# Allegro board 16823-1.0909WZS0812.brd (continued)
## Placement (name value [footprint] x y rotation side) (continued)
PC1014  SC22U6D3V3MX-1-GP  [C603H40]  113.52 118.72 270 top
PC1015  SC22U6D3V3MX-1-GP  [C603H40]  113.52 117.43 270 top
PC1016  SC22U6D3V3MX-1-GP  [C603H40]  113.11 115.57 180 top
PC1017  SC22U6D3V3MX-1-GP  [C603H40]  110.52 114.94 180 top
PC1018  SC22U6D3V3MX-1-GP  [C603H40]  111.82 114.94 179.7 top
PC1019  SC22U6D3V3MX-1-GP  [C603H40]  109.86 111.81 270 top
PC1020  SC22U6D3V3MX-1-GP  [C603H40]  121.5 118.87 89.9 top
PC1021  SC22U6D3V3MX-1-GP  [C603H40]  121.49 117.6 90 top
PC1022  SC22U6D3V3MX-1-GP  [C603H40]  121.5 116.31 90 top
PC1023  SCD1U25V2KX-GP  [C402H22]  123.38 85.3 110 top
PC1024  SC22U6D3V3MX-1-GP  [C603H40]  121.5 115.01 90 top
PC1025  SC22U6D3V3MX-1-GP  [C603H40]  121.5 113.72 89.9 top
PC1026  SC22U6D3V3MX-1-GP  [C603H40]  121.72 109.73 90 top
PC1027  SC22U6D3V3MX-1-GP  [C603H40]  143.09 80.09 90 top
PC1028  SC22U6D3V3MX-1-GP  [C603H40]  109.86 110.52 270 top
PC1030  SC22U6D3V3MX-1-GP  [C603H40]  117.86 106.91 20 bottom
PC1031  SC22U6D3V3MX-1-GP  [C603H40]  114.15 105.52 20 bottom
PC1032  SC22U6D3V3MX-1-GP  [C603H40]  116.65 106.45 20 bottom
PC1033  SC22U6D3V3MX-1-GP  [C603H40]  119.11 107.36 20 bottom
PC1034  SC22U6D3V3MX-1-GP  [C603H40]  113.11 115.57 0.2 bottom
PC1035  SC22U6D3V3MX-1-GP  [C603H40]  111.82 114.94 0 bottom
PC1036  SC22U6D3V3MX-1-GP  [C603H40]  120.32 107.83 20 bottom
PC1037  SC22U6D3V3MX-1-GP  [C603H40]  115.4 106 20 bottom
PC1038  SCD1U25V2KX-GP  [C402H22]  109.79 108.59 270 top
PC1039  SC22U6D3V3MX-1-GP  [C603H40]  110.52 114.94 0 bottom
PC1040  SC22U6D3V3MX-1-GP  [C603H40]  140.24 106.81 0 bottom
PC1041  SC22U6D3V3MX-1-GP  [C603H40]  125.91 93.93 290 top
PC1042  SC22U6D3V3MX-1-GP  [C603H40]  143.31 87.2 0 top
PC1043  SC22U6D3V3MX-1-GP  [C603H40]  144.81 85.32 180 top
PC1044  SC22U6D3V3MX-1-GP  [C603H40]  109.86 113.11 269.9 top
PC1045  SC22U6D3V3MX-1-GP  [C603H40]  125.77 84.39 200 top
PC1046  SC22U6D3V3MX-1-GP  [C603H40]  143.72 90.88 180.1 top
PC1047  SC10U6D3V3MX-GP  [C603H38]  139.22 81.43 90 top
PC1048  SC22U6D3V3MX-1-GP  [C603H40]  102.6 115.54 270 top
PC1049  SC22U6D3V3MX-1-GP  [C603H40]  102.6 114.27 270 top
PC1050  SC22U6D3V3MX-1-GP  [C603H40]  121.25 82.8 20 top
PC1051  SC22U6D3V3MX-1-GP  [C603H40]  107.3 114 90 top
PC1052  SC10U6D3V3MX-GP  [C603H38]  143.06 78.77 90 top
PC1101  SC1U10V2KX-1GP  [C402H22]  127.24 87.28 290 top
PC1102  SC22U6D3V3MX-1-GP  [C603H40]  145.63 92.99 90.1 top
PC1103  SC22U6D3V3MX-1-GP  [C603H40]  118.96 88.19 110 top
PC4301  SC1U50V5ZY-1-GP-U  [C805H58]  137.55 163.32 270 top
PC4302  SCD1U50V3KX-GP  [C603H36]  140.29 172.11 90 top
PC4303  SCD01U50V2KX-1GP  [C402H22]  145.88 157.2 0 top
PC4304  SCD01U50V2KX-1GP  [C402H22]  144.99 157.2 0 top
PC4305  SCD01U50V2KX-1GP  [C402H22]  144.1 157.2 0 top
PC4306  SC10U25V5KX-GP  [C805H56]  147.28 157.23 0 top
PC4401  SCD1U50V3KX-GP  [C603H36]  155.56 148.9 270 top
PC4402  SCD1U25V2KX-GP  [C402H22]  154.82 153.47 180 top
PC4403  SCD1U50V3KX-GP  [C603H36]  153.73 154.99 180 top
PC4404  SCD1U50V3KX-GP  [C603H36]  153.73 152.58 0 top
PC4406  SC10U25V5KX-L-GP  [C805H56]  159.7 159.41 0 top
PC4407  SC1U10V2KX-1GP  [C402H22]  162.72 156.47 180 top
PC4408  SC4D7U25V5KX-GP  [C805H54]  161.6 159.41 0 top
PC4409  SCD1U50V3KX-GP  [C603H36]  153.37 161.44 270 top
PC4410  SCD47U25V3KX-1GP  [C603H36]  155.38 156.52 180 top
PC4411  SCD047U25V2KX-GP  [C402H22]  161.27 157.36 270 top
PC4412  SCD01U50V2KX-1GP  [C402H22]  157.39 146.31 0 top
PC4413  SC3300P50V3KX-1GP  [C603H36]  159.06 156.8 0 top
PC4415  SC10U25V5KX-L-GP  [C805H56]  167.06 175.82 90 top
PC4416  SC10U25V5KX-GP  [C805H56]  155.18 174.17 270 top
PC4417  SC10U25V5KX-GP  [C805H56]  155.18 175.97 270 top
PC4418  SC10U25V5KX-L-GP  [C805H56]  167.06 177.62 90 top
PC4419  SCD1U50V3KX-GP  [C603H36]  167.09 173.1 270 bottom
PC4420  SCD1U25V2KX-GP  [C402H22]  166.81 143 180 top
PC4421  SCD1U25V2KX-GP  [C402H22]  167.47 148.21 0 top
PC4422  SC100P50V2JN-3GP  [C402H22]  159.87 146.31 0 top
PC4423  SCD1U25V2KX-GP  [C402H22]  166.81 146.53 0 top
PC4425  SCD01U50V2KX-1GP  [C402H22]  164.9 153.21 0 top
PC4426  SC10U25V5KX-GP  [C805H56]  154.41 169.75 180 top
PC4433  SCD47U6D3V2KX-GP  [C402H22]  175.6 156.29 180 top
PC4434  SC1U25V3KX-1-GP  [C603H36]  173.26 152 180 top
PC4435  SC2200P50V2KX-2DLGP  [C402H22]  170.92 160.99 270 bottom
PC4501  SCD1U16V2KX-3GP  [C402H22]  50.43 57.13 270 top
PC4509  SC4D7U25V5KX-GP  [C805H54]  46.9 54.43 0 top
PC4516  SCD1U50V3KX-GP  [C603H36]  51.47 44.2 180 top
PC4517  SCD1U16V2KX-3GP  [C402H22]  31.45 59.62 270 top
PC4518  SCD1U16V2KX-3GP  [C402H22]  35.87 40.24 270 bottom
PC4519  SC10U25V5KX-GP  [C805H56]  46.36 49.68 270 top
PC4520  SC330P50V3KX-GP  [C603]  43.29 49.46 270 bottom
PC4522  SC18P50V2JN-1-GP  [C402H22]  56.9 44.07 270 top
PC4523  SC18P50V2JN-1-GP  [C402H22]  53.93 46.87 180 top
PC4524  SC4D7U6D3V3KX-GP  [C603H36]  46.54 47.27 270 top
PC4525  SCD1U50V3KX-GP  [C603H36]  45.3 54.38 0 top
PC4526  SC4D7U6D3V3KX-GP  [C603H36]  52.38 49.51 90 bottom
PC4527  SC10U25V5KX-GP  [C805H56]  48.65 42.45 180 top
PC4528  SC10U25V5KX-GP  [C805H56]  48.8 54.43 0 top
PC4529  SC4D7U25V5KX-GP  [C805H54]  46.82 42.45 180 top
PC4530  SCD1U50V3KX-GP  [C603H36]  45.27 42.65 180 top
PC4531  SCD01U50V2KX-1GP  [C402H22]  46.21 48.34 270 top
PC4535  SCD1U50V3KX-GP  [C603H36]  51.65 52.86 0 top
PC4536  SC560P50V-GP  [C603]  43.85 41.94 0 bottom
PC5003  SC10U6D3V3MX-GP  [C603H38]  140.42 125.12 270 bottom
PC5004  SC10U6D3V3MX-GP  [C603H38]  135.92 129.39 270 top
PC5005  SC22U6D3V5MX-2GP  [C805H58]  131.68 120.3 90 bottom
PC5006  SC22U6D3V5MX-2GP  [C805H58]  131.68 118.39 90 bottom
PC5007  SC10U6D3V3MX-GP  [C603H38]  129.67 124 180 bottom
PC5008  SC10U6D3V3MX-GP  [C603H38]  130.97 124 180 bottom
PC5009  SC22U6D3V5MX-2GP  [C805H58]  143.95 125.94 0 top
PC5010  SC10U6D3V3MX-GP  [C603H38]  131.83 133.45 90 top
PC5011  SC2200P50V2KX-2GP  [C402H22]  130.66 131.4 90 top
PC5012  SC2200P50V2KX-2GP  [C402H22]  140.06 121.46 90 bottom
PC5013  SC2200P50V2KX-2GP  [C402H22]  140.06 123.17 270 bottom
PC5014  SC680P50V2KX-2GP  [C402H22]  125.94 126.82 270 bottom
PC5015  SCD1U25V2KX-GP  [C402H22]  134.86 136.04 90 bottom
PC5016  SC1200P50V2KX-1GP  [C402H24]  125.94 128.55 270 bottom
PC5017  SC22U6D3V5MX-2GP  [C805H58]  145.52 134.44 0 bottom
PC5018  SC22U6D3V5MX-2GP  [C805H58]  143.62 134.44 0 bottom
PC5019  SC22U6D3V5MX-2GP  [C805H58]  130.56 136.5 0 bottom
PC5020  SC22U6D3V5MX-2GP  [C805H58]  143.95 125.94 180 bottom
PC5021  SCD1U25V2KX-GP  [C402H22]  133.15 136.88 270 bottom
PC5022  SC22U6D3V5MX-2GP  [C805H58]  145.78 125.94 180 bottom
PC5023  SC2D2U10V3KX-1GP  [C603H36]  135.92 133.3 270 top
PC5024  SC10U6D3V3MX-GP  [C603H38]  135.92 130.69 270 top
PC5025  SC10U6D3V3MX-GP  [C603H38]  135.92 126.82 270 top
PC5026  SC2200P50V2KX-2GP  [C402H22]  133.94 127.59 180 top
PC5027  SC2200P50V2KX-2GP  [C402H22]  130.66 132.39 90 top
PC5028  SC1U10V2KX-1GP  [C402H22]  133.87 133.43 90 top
PC5029  SCD1U25V2KX-GP  [C402H22]  138.03 122.33 270 bottom
PC5030  SC22U6D3V5MX-2GP  [C805H58]  145.85 125.94 0 top
PC5031  SC22U6D3V5MX-2GP  [C805H58]  135.01 118.42 270 bottom
PC5032  SC22U6D3V5MX-2GP  [C805H58]  134.6 120.3 270 bottom
PC5033  SC10P50V2JN-4GP  [C402H22]  127.21 128.17 0 bottom
PC5034  SC2D2U10V3KX-1GP  [C603H36]  135.92 131.98 270 top
PC5035  SC22U6D3V3MX-1-GP  [C603H40]  144.99 129.31 180 top
PC5036  SC22U6D3V3MX-1-GP  [C603H40]  143.7 129.31 180 top
PC5101  SC22U6D3V3MX-1-GP  [C603H40]  86.95 54.03 180 top
PC5102  SC10U25V5KX-GP  [C805H56]  58.02 36.12 180 top
PC5103  SC1U10V2KX-1GP  [C402H22]  126.5 135.28 90 top
PC5104  SC10U25V5KX-GP  [C805H56]  106.76 132.13 270 top
PC5105  SC1KP50V2KX-1GP  [C402H22]  119.64 125.45 90 top
PC5106  SCD1U50V3KX-GP  [C603H36]  137.9 120.68 180 bottom
PC5107  SC22U6D3V3MX-1-GP  [C603H40]  86.75 42.98 0 top
PC5108  SC22U6D3V3MX-1-GP  [C603H40]  88.3 54.03 180 top
PC5109  SC1U10V2KX-1GP  [C402H22]  54.64 33.56 180 top
PC5110  SC22U6D3V3MX-1-GP  [C603H40]  76.44 40.77 0 top
PC5112  SCD1U25V2KX-GP  [C402H22]  69.81 44.02 90 bottom
PC5113  SC10U25V5KX-GP  [C805H56]  115.78 132.36 90 top
PC5114  SC10U25V5KX-GP  [C805H56]  115.78 132.36 270 bottom
PC5115  SCD1U50V3KX-GP  [C603H36]  56.04 32.08 180 bottom
PC5116  SCD1U50V3KX-GP  [C603H36]  108.31 135.89 90 bottom
PC5117  SC22U6D3V3MX-1-GP  [C603H40]  85.58 54.03 180 top
PC5118  SC22U6D3V3MX-1-GP  [C603H40]  84.13 42.98 0 top
PC5119  SC10U25V5KX-GP  [C805H56]  61.7 36.12 180 top
PC5120  SC22U6D3V3MX-1-GP  [C603H40]  88.12 43 0 top
PC5121  SCD1U50V3KX-GP  [C603H36]  119.23 135.28 90 top
PC5122  SC1KP50V2KX-1GP  [C402H22]  66.71 34.44 0 bottom
PC5123  SC22U6D3V3MX-1-GP  [C603H40]  78.59 40.74 0 top
PC5124  SC1U10V2KX-1GP  [C402H22]  101.05 136.5 90 bottom
PC5125  SC1KP50V2KX-1GP  [C402H22]  105.49 127.46 180 top
PC5126  SC22U6D3V3MX-1-GP  [C603H40]  85.45 42.98 0 top
PC5127  SC22U6D3V3MX-1-GP  [C603H40]  70.92 45.67 0 bottom
PC5128  SC10U25V5KX-GP  [C805H56]  59.85 36.12 180 top
PC5129  SC22U6D3V3MX-1-GP  [C603H40]  72.19 45.67 0 bottom
PC5130  SC22U6D3V3MX-1-GP  [C603H40]  73.46 45.67 0 bottom
PC5131  SC10U25V5KX-GP  [C805H56]  115.78 134.16 270 bottom
PD4301  SD103AWS-2-GP  [SOD323AKH38]  131.83 173.48 270 bottom
PD4302  LBAV99LT1G-1-GP  [SOT23-2D4-312H44]  128.91 161.75 90 top
PD4303  PESD24VS2UT-GP  [SOT-23-10H44]  132.29 167.52 270 top
PD4304  SMF18A-GP  [SOD123AK-2H43]  167.06 173.46 270 top
PD4401  SD103AWS-2-GP  [SOD323AKH38]  163.91 156.47 90 bottom
PD4404  1N4148WS-7-F-GP  [SOD323AKH42]  173.21 162.69 0 top
PG4402  GAP-CLOSE-PWR-3-GP  [GAP-CLOSE-PWR-3]  150.71 164.87 270 top
PG4403  GAP-CLOSE-PWR-3-GP  [GAP-CLOSE-PWR-3]  152.43 164.92 270 top
PG4407  GAP-CLOSE-PWR-3-GP  [GAP-CLOSE-PWR-3]  163.43 146.38 270 top
PG4408  GAP-CLOSE-PWR-3-GP  [GAP-CLOSE-PWR-3]  162.49 146.38 270 top
PG4409  GAP-CLOSE-PWR-3-GP  [GAP-CLOSE-PWR-3]  161.27 167.36 90 bottom
PG4410  GAP-CLOSE-PWR-3-GP  [GAP-CLOSE-PWR-3]  159.49 167.36 90 bottom
PG4411  GAP-CLOSE-PWR-3-GP  [GAP-CLOSE-PWR-3]  162.54 151.97 0 bottom
PG4517  GAP-CLOSE-PWR-3-GP  [GAP-CLOSE-PWR-3]  31.5 55.07 0 top
PG4518  GAP-CLOSE-PWR-3-GP  [GAP-CLOSE-PWR-3]  45.12 38.46 90 top
PG4519  GAP-CLOSE-PWR-3-GP  [GAP-CLOSE-PWR-3]  29.08 47.14 180 top
PG4520  GAP-CLOSE-PWR-3-GP  [GAP-CLOSE-PWR-3]  45.88 38.46 90 top
PG4521  GAP-CLOSE-PWR-3-GP  [GAP-CLOSE-PWR-3]  47.33 58.98 270 top
PG4522  GAP-CLOSE-PWR-3-GP  [GAP-CLOSE-PWR-3]  31.5 55.83 0 top
PG4523  GAP-CLOSE-PWR-3-GP  [GAP-CLOSE-PWR-3]  29.08 46.38 180 top
PG4524  GAP-CLOSE-PWR-3-GP  [GAP-CLOSE-PWR-3]  45.04 58.98 270 top
PG4525  GAP-CLOSE-PWR-3-GP  [GAP-CLOSE-PWR-3]  46.57 58.98 270 top
PG4526  GAP-CLOSE-PWR-3-GP  [GAP-CLOSE-PWR-3]  31.5 57.36 0 top
PG4527  GAP-CLOSE-PWR-3-GP  [GAP-CLOSE-PWR-3]  29.06 41.05 180 top
PG4528  GAP-CLOSE-PWR-3-GP  [GAP-CLOSE-PWR-3]  31.5 58.12 0 top
PG4529  GAP-CLOSE-PWR-3-GP  [GAP-CLOSE-PWR-3]  31.5 56.59 0 top
PG4531  GAP-CLOSE-PWR-3-GP  [GAP-CLOSE-PWR-3]  45.8 58.98 270 top
PG4532  GAP-CLOSE-PWR-3-GP  [GAP-CLOSE-PWR-3]  28.15 41.35 180 bottom
PG4533  GAP-CLOSE-PWR-3-GP  [GAP-CLOSE-PWR-3]  29.08 45.61 180 top
PG4534  GAP-CLOSE-PWR-3-GP  [GAP-CLOSE-PWR-3]  46.64 38.46 90 top
PG4535  GAP-CLOSE-PWR-3-GP  [GAP-CLOSE-PWR-3]  32.95 60.12 180 bottom
PG4536  GAP-CLOSE-PWR-3-GP  [GAP-CLOSE-PWR-3]  47.4 38.46 90 top
PG4537  GAP-CLOSE-PWR-3-GP  [GAP-CLOSE-PWR-3]  29.06 41.81 180 top
PG4538  GAP-CLOSE-PWR-3-GP  [GAP-CLOSE-PWR-3]  29.06 42.57 180 top
PG4540  GAP-CLOSE-PWR-3-GP  [GAP-CLOSE-PWR-3]  29.06 40.29 180 top
PG4541  GAP-CLOSE-PWR-3-GP  [GAP-CLOSE-PWR-3]  29.06 43.33 180 top
PG4542  GAP-CLOSE-PWR-3-GP  [GAP-CLOSE-PWR-3]  48.17 38.46 90 top
PG4543  GAP-CLOSE-PWR-3-GP  [GAP-CLOSE-PWR-3]  48.93 38.46 90 top
PG4544  GAP-CLOSE-PWR-3-GP  [GAP-CLOSE-PWR-3]  29.06 44.1 180 top
PG4545  GAP-CLOSE-PWR-3-GP  [GAP-CLOSE-PWR-3]  29.06 44.86 180 top
PG5003  GAP-CLOSE-PWR-3-GP  [GAP-CLOSE-PWR-3]  147.48 126.57 0 bottom
PG5004  GAP-CLOSE-PWR-3-GP  [GAP-CLOSE-PWR-3]  147.48 127.33 0 bottom
PG5005  GAP-CLOSE-PWR-3-GP  [GAP-CLOSE-PWR-3]  147.48 128.09 0 bottom
PG5007  GAP-CLOSE-PWR-3-GP  [GAP-CLOSE-PWR-3]  134.5 116.59 270 bottom
PG5008  GAP-CLOSE-PWR-3-GP  [GAP-CLOSE-PWR-3]  133.74 116.59 270 bottom
PG5009  GAP-CLOSE-PWR-3-GP  [GAP-CLOSE-PWR-3]  132.98 116.59 270 bottom
PG5011  GAP-CLOSE-PWR-3-GP  [GAP-CLOSE-PWR-3]  147.2 132.87 0 bottom
PG5012  GAP-CLOSE-PWR-3-GP  [GAP-CLOSE-PWR-3]  147.2 132.11 0 bottom
PG5014  GAP-CLOSE-PWR-3-GP  [GAP-CLOSE-PWR-3]  128.1 137.42 0 bottom
PG5016  GAP-CLOSE-PWR-3-GP  [GAP-CLOSE-PWR-3]  128.1 136.48 180 bottom
PG5101  GAP-CLOSE-PWR-3-GP  [GAP-CLOSE-PWR-3]  121.62 111.74 180 top
PG5102  GAP-CLOSE-PWR-3-GP  [GAP-CLOSE-PWR-3]  74.63 45.65 270 bottom
PG5103  GAP-CLOSE-PWR-3-GP  [GAP-CLOSE-PWR-3]  107.32 112.85 180 top
PG5104  GAP-CLOSE-PWR-3-GP  [GAP-CLOSE-PWR-3]  91.07 51.69 0 top
PG5105  GAP-CLOSE-PWR-3-GP  [GAP-CLOSE-PWR-3]  91.07 52.45 0 top
PG5106  GAP-CLOSE-PWR-3-GP  [GAP-CLOSE-PWR-3]  91.07 53.22 0 top
PG5107  GAP-CLOSE-PWR-3-GP  [GAP-CLOSE-PWR-3]  90.91 44.43 0 top
PG5108  GAP-CLOSE-PWR-3-GP  [GAP-CLOSE-PWR-3]  90.91 43.66 0 top
PG5109  GAP-CLOSE-PWR-3-GP  [GAP-CLOSE-PWR-3]  90.91 45.19 0 top
PG5110  GAP-CLOSE-PWR-3-GP  [GAP-CLOSE-PWR-3]  105.47 124.36 90 bottom
PG5111  GAP-CLOSE-PWR-3-GP  [GAP-CLOSE-PWR-3]  117.66 121.69 90 bottom
PG5112  GAP-CLOSE-PWR-3-GP  [GAP-CLOSE-PWR-3]  71.18 37.92 270 bottom
PG5113  GAP-CLOSE-PWR-3-GP  [GAP-CLOSE-PWR-3]  110.47 133.99 270 top
PG5114  GAP-CLOSE-PWR-3-GP  [GAP-CLOSE-PWR-3]  114.94 135.97 270 bottom
PG5115  GAP-CLOSE-PWR-3-GP  [GAP-CLOSE-PWR-3]  61.32 30.36 90 top
PG5116  GAP-CLOSE-PWR-3-GP  [GAP-CLOSE-PWR-3]  113.42 135.97 270 bottom
PG5117  GAP-CLOSE-PWR-3-GP  [GAP-CLOSE-PWR-3]  114.18 135.97 270 bottom
PG5118  GAP-CLOSE-PWR-3-GP  [GAP-CLOSE-PWR-3]  62.08 30.36 90 top
PG5119  GAP-CLOSE-PWR-3-GP  [GAP-CLOSE-PWR-3]  112.66 135.97 270 bottom
PG5120  GAP-CLOSE-PWR-3-GP  [GAP-CLOSE-PWR-3]  109.71 133.99 270 top
PG5121  GAP-CLOSE-PWR-3-GP  [GAP-CLOSE-PWR-3]  120.76 55.76 270 top
PG5122  GAP-CLOSE-PWR-3-GP  [GAP-CLOSE-PWR-3]  121.52 55.76 270 top
PG5123  GAP-CLOSE-PWR-3-GP  [GAP-CLOSE-PWR-3]  122.28 55.76 270 top
PG5124  GAP-CLOSE-PWR-3-GP  [GAP-CLOSE-PWR-3]  123.04 55.76 270 top
PG5125  GAP-CLOSE-PWR-3-GP  [GAP-CLOSE-PWR-3]  123.81 55.76 270 top
PG5126  GAP-CLOSE-PWR-3-GP  [GAP-CLOSE-PWR-3]  124.57 55.76 270 top
PG5127  GAP-CLOSE-PWR-3-GP  [GAP-CLOSE-PWR-3]  91.07 49.41 0 top
PG5128  GAP-CLOSE-PWR-3-GP  [GAP-CLOSE-PWR-3]  91.07 50.93 0 top
PG5129  GAP-CLOSE-PWR-3-GP  [GAP-CLOSE-PWR-3]  91.07 50.17 0 top
PL4401  IND-5D6UH-45-GP-U  [L686647-127318H119]  166.89 168.23 90 bottom
PL4501  IND-2D2UH-46-GP-U1  [L7066-1830-UH119]  37.02 44.48 90 bottom
PL4502  IND-2D2UH-46-GP-U1  [L7066-1830-UH119]  37.02 52.35 270 bottom
PL5001  IND-2D2UH-338-GP  [L2520-D620H48]  140.75 131.8 270 bottom
PL5002  IND-1UH-352-GP  [L32250525H48]  140.7 127.66 270 bottom
PL5003  IND-1UH-300-GP  [L2520-D620H48]  133.26 123.22 180 bottom
PL5101  IND-D56UH-36-GP  [L7066-1630-1H119]  105.04 122.91 180 bottom
PL5102  IND-D47UH-22-GP-U  [L7066-1830-UH119]  71.25 39.02 0 bottom
PL5103  IND-D22UH-37-GP  [L7066-1830-UH119]  117.63 120.55 180 bottom
PQ4301  DMN5L06K-7-GP  [SOT23DGS2D4H48]  128.2 167.59 270 top
PQ4302  LMBT3904LT1G-GP  [SOT23CBE2D4H44]  133.03 161.95 270 top
PQ4304  LMUN5212T1G-GP  [SOT323CBE2D2H40]  150.88 173.81 0 top
PQ4305  LTA024EUB-FS8-GP  [SC70-2D2-312H44]  136.23 167.36 90 top
PQ4306  2N7002KDW-GP  [SOT-363H44]  147.45 172.9 270 top
PQ4402  2N7002KDW-1-GP  [SOT-363H44]  172.07 155.7 270 top
PQ4407  2N7002KDW-1-GP  [SOT-363H44]  152.56 149.79 90 top
PQ4408  2N7002KDW-1-GP  [SOT-363H44]  167.11 153.67 270 top
PQ4409  LMBT3906LT1G-1-GP  [SOT23CBE2D4H44]  176.26 164.85 0 top
PQ4410  2N7002KDW-1-GP  [SOT-363H44]  169.02 150.62 270 top
PQ4414  2N7002K-2-GP  [SOT23DGS2D4H44]  176.11 159.03 0 top
PR4302  15KR2F-GP  [R402H16]  132.85 165.03 90 top
PR4303  10KR2J-3-GP  [R402H16]  135.47 161.52 180 top
PR4304  2K2R2J-2-GP  [R402H16]  128.79 164.16 270 top
PR4305  33R2J-2-GP  [R402H16]  127.26 164.67 0 top
PR4306  33R2J-2-GP  [R402H16]  128.7 165.03 270 top
PR4307  240KR3-GP  [R603H22]  137.35 164.92 270 top
PR4308  47KR3J-L-GP  [R603H22]  134.91 164.92 270 top
PR4309  100KR2J-1-GP  [R402H16]  131.1 165.03 90 top
PR4312  100KR2J-1-GP  [R402H16]  140.42 170.99 90 top
PR4313  0R0402-PAD-2-GP  [0R0402-PAD-1]  141.92 172.29 180 top
PR4314  3K3R6J-GP  [R1206H28]  142.22 163.71 90 top
PR4317  0R0603-PAD-2-GP-U  [0R0603-PAD-1-U]  129.14 173.1 180 bottom
PR4401  10KR2J-3-GP  [R402H16]  172.57 157.86 270 top
PR4402  D01R3721F-GP-U  [R3720H40]  151.54 167.16 90 top
PR4403  100KR2J-1-GP  [R402H16]  146.84 164.85 270 top
PR4404  3KR5J-GP  [R805H24]  168.69 156.11 90 top
PR4405  470KR2J-2-GP  [R402H16]  168.31 157.53 90 top
PR4406  0R2J-2-GP  [R402H16]  155.71 153.47 0 top
PR4407  309KR2F-GP  [R402H16]  156.57 146.31 180 top
PR4408  20R5J-GP  [R805H24]  156.98 156.69 0 top
PR4409  0R0603-PAD-2-GP-U  [0R0603-PAD-1-U]  161.07 156.26 90 top
PR4411  102KR2F-GP  [R402H16]  161.58 146.31 0 top
PR4412  3K3R2F-2-GP  [R402H16]  162.52 144.55 180 top
PR4413  169KR2F-L-GP  [R402H16]  160.31 145.01 270 top
PR4414  3D3MR2J-GP  [R402H16]  160.31 144.17 90 top
PR4415  3K3R2F-2-GP  [R402H16]  163.33 144.55 180 top
PR4416  D01R3721F-GP-U  [R3720H40]  160.38 169.6 90 bottom
PR4417  100KR2J-1-GP  [R402H16]  165.18 146.26 180 top
PR4418  0R2J-2-GP  [R402H16]  166 146.26 180 top
PR4419  100KR2J-1-GP  [R402H16]  164.9 150.88 180 top
PR4420  7D5R2F-GP  [R402H16]  166.22 147.78 90 top
PR4421  10R2F-L-GP  [R402H14]  166.22 148.59 90 top
PR4422  0R0402-PAD-2-GP  [0R0402-PAD-1]  159.04 146.31 0 top
PR4423  59KR2F-GP  [R402H16]  164.32 146.26 0 top
PR4424  8K45R2F-2-GP  [R402H16]  160.74 146.31 0 top
PR4425  100KR2J-1-GP  [R402H16]  165.31 156.44 180 top
PR4426  0R0402-PAD-2-GP  [0R0402-PAD-1]  169.43 153.16 0 top
PR4427  78K7R2F-GP  [R402H16]  155.73 151.74 90 top
PR4429  309KR2F-GP  [R402H16]  155.73 150.9 270 top
PR4430  100KR2J-1-GP  [R402H16]  163.56 156.47 180 top
PR4431  47KR2F-GP  [R402H16]  158.2 146.31 0 top
PR4432  120KR2F-L-GP  [R402H16]  158.58 143.84 270 top
PR4433  120KR2F-L-GP  [R402H16]  155.53 147.83 270 top
PR4434  100KR2J-1-GP  [R402H16]  155.76 146.31 180 top
PR4435  10KR2F-2-GP  [R402H16]  165.62 144.96 90 top
PR4436  120KR2F-L-GP  [R402H16]  171.99 153.19 0 top
PR4437  160KR2F-GP  [R402H16]  158.53 152.1 270 bottom
PR4438  100KR2J-1-GP  [R402H16]  158.58 142.98 270 top
PR4439  100KR2J-1-GP  [R402H16]  164.45 156.44 180 top
PR4440  2D2R5F-2-GP  [R805H24]  170.82 162.87 180 bottom
PR4464  680KR2J-GP  [R402H16]  175.88 167.26 270 top
PR4465  0R2J-2-GP  [R402H16]  177.4 161.6 90 top
PR4466  0R2J-2-GP  [R402H16]  168.74 148.69 90 top
PR4468  0R2J-2-GP  [R402H16]  175.6 161.6 270 top
PR4469  100KR2J-1-GP  [R402H16]  177.4 162.44 270 top
PR4470  1MR2J-1-GP  [R402H16]  175.62 162.44 270 top
PR4471  100KR2F-L1-GP  [R402H16]  171.23 150.95 180 top
PR4472  100KR2F-L1-GP  [R402H16]  175.17 155.02 90 top
PR4473  10KR2F-2-GP  [R402H16]  174.71 154.03 90 top
PR4474  100KR2J-1-GP  [R402H16]  176.49 156.29 0 top
PR4475  0R2J-2-GP  [R402H16]  165.72 150.88 0 top
PR4476  0R2J-2-GP  [R402H16]  166.73 150.88 0 top
PR4501  0R2J-2-GP  [R402H16]  50.81 52.15 90 bottom
PR4502  0R0402-PAD-2-GP  [0R0402-PAD-1]  51.85 44.71 0 bottom
PR4503  0R2J-2-GP  [R402H16]  53.6 52.53 0 top
PR4504  0R2J-2-GP  [R402H16]  49.72 47.88 270 bottom
PR4505  0R0402-PAD-2-GP  [0R0402-PAD-1]  52.69 51.31 90 bottom
PR4506  10KR2J-3-GP  [R402H16]  50.43 57.96 90 top
PR4512  6K65R2F-GP  [R402H16]  54.67 49 270 top
PR4517  100KR2F-L1-GP  [R402H16]  54.87 51.79 90 top
PR4523  10KR2F-2-GP  [R402H16]  54.62 50.37 180 top
PR4524  1D5R3-GP  [R603H22]  50.2 44.2 0 top
PR4525  0R2J-2-GP  [R402H16]  56.9 43.23 90 top
PR4526  9K76R2F-1-GP  [R402H16]  53.07 45.19 270 top
PR4527  15K4R2F-GP  [R402H16]  54.31 43.82 90 top
PR4528  1D5R3-GP  [R603H22]  50.35 53.06 0 top
PR4529  2D2R5F-2-GP  [R805H24]  43.06 39.83 270 bottom
PR4530  0R2J-2-GP  [R402H16]  48.95 48.92 90 bottom
PR4531  130KR2F-GP  [R402H16]  53.35 46.38 180 bottom
PR4533  2D2R5F-2-GP  [R805H24]  42.63 51.56 180 bottom
PR4534  100KR2J-1-GP  [R402H16]  51.7 54.66 90 top
PR4535  0R2J-2-GP  [R402H16]  54.77 46.87 0 top
PR5001  0R0402-PAD-2-GP  [0R0402-PAD-1]  131.88 136.48 0 bottom
PR5004  100R2F-L1-GP-U  [R402H14]  125.94 125.15 270 bottom
PR5005  0R0402-PAD-2-GP  [0R0402-PAD-1]  141.82 121.46 90 bottom
PR5007  2D2R2J-GP  [R402H16]  134.86 137.75 270 bottom
PR5008  2D2R2J-GP  [R402H16]  133.15 137.75 90 bottom
PR5010  0R0402-PAD-2-GP  [0R0402-PAD-1]  131.68 117.02 270 bottom
PR5012  100R2F-L1-GP-U  [R402H14]  140.06 124.03 90 bottom
PR5013  0R0402-PAD-2-GP  [0R0402-PAD-1]  140.06 122.3 90 bottom
PR5014  100KR2J-1-GP  [R402H16]  134.86 136.88 270 bottom
PR5016  2K2R2J-2-GP  [R402H16]  125.74 127.1 90 top
PR5017  0R0402-PAD-2-GP  [0R0402-PAD-1]  141.38 133.91 270 bottom
PR5018  100KR2J-1-GP  [R402H16]  133.15 136.04 90 bottom
PR5019  549R2F-GP  [R402H16]  125.94 125.99 90 bottom
PR5020  10KR2F-2-GP  [R402H16]  125.94 127.66 90 bottom
PR5021  38K3R2F-GP  [R402H16]  138.79 136.6 0 bottom
PR5023  0R0402-PAD-2-GP  [0R0402-PAD-1]  141.76 136.17 270 bottom
PR5024  21KR2F-GP  [R402H16]  140.52 136.6 0 bottom
PR5025  2K2R2J-2-GP  [R402H16]  125.74 127.97 90 top
PR5029  10KR2J-3-GP  [R402H16]  144.74 130.79 90 bottom
PR5030  10KR2J-3-GP  [R402H16]  125.71 125.4 270 top
PR5031  2D2R3J-2-GP  [R603H22]  134.5 136.15 270 top
PR5032  9K1R2F-1-GP  [R402H16]  128.2 127.56 0 bottom
PR5033  0R0402-PAD-2-GP  [0R0402-PAD-1]  127.46 130.3 90 bottom
PR5034  100R2F-L1-GP-U  [R402H14]  127.19 132.01 90 bottom
PR5035  0R0402-PAD-2-GP  [0R0402-PAD-1]  127.46 131.17 90 bottom
PR5036  15K8R2F-GP  [R402H16]  139.66 136.6 0 bottom
PR5037  0R0402-PAD-2-GP  [0R0402-PAD-1]  137.9 136.6 0 bottom
PR5038  0R0402-PAD-2-GP  [0R0402-PAD-1]  136.15 136.6 0 bottom
PR5039  0R0402-PAD-2-GP  [0R0402-PAD-1]  137.01 136.6 0 bottom
PR5040  0R0402-PAD-2-GP  [0R0402-PAD-1]  135.59 124.49 180 bottom
PR5041  0R0402-PAD-2-GP  [0R0402-PAD-1]  144.74 129.06 270 bottom
PR5042  0R0402-PAD-2-GP  [0R0402-PAD-1]  125.74 126.24 270 top
PR5043  0R0402-PAD-2-GP  [0R0402-PAD-1]  125.94 124.28 90 bottom
PR5044  1KR2J-1-GP  [R402H16]  144.74 129.92 90 bottom
PR5045  0R2J-2-GP  [R402H16]  127.46 129.47 90 bottom
PR5046  0R2J-2-GP  [R402H16]  52.71 55.53 270 top
PR5101  2D2R3J-2-GP  [R603H22]  126.7 136.4 270 top
PR5102  2D2R5F-2-GP  [R805H24]  121.47 126.34 180 top
PR5103  2D2R3J-2-GP  [R603H22]  100.82 135.41 270 bottom
PR5104  2D2R3J-2-GP  [R603H22]  53.98 31.98 90 top
PR5105  0R0603-PAD-2-GP-U  [0R0603-PAD-1-U]  108.31 134.6 270 bottom
PR5106  0R0603-PAD-2-GP-U  [0R0603-PAD-1-U]  58.15 32.08 0 bottom
PR5107  NTC-10K-47-GP  [NTC-402H24-U]  122 120.86 180 bottom
PR5108  562R2F-GP  [R402H16]  137.6 119.05 270 bottom
PR5109  0R0603-PAD-2-GP-U  [0R0603-PAD-1-U]  119.23 133.78 270 top
PR5110  2K94R2F-GP  [R402H16]  136.28 123.22 270 bottom
PR5111  226R2F-GP  [R402H16]  136.28 122.35 90 bottom
PR5112  2D2R5F-2-GP  [R805H24]  65.31 35.71 0 bottom
PR5113  0R0402-PAD-2-GP  [0R0402-PAD-1]  138.03 123.22 90 bottom
PR5114  2D2R5F-2-GP  [R805H24]  105.49 129.75 180 top
PT4501  SE220U6D3VM-38-GP  [SE361414H178]  27.72 41.3 90 bottom
PT4502  SE220U6D3VM-38-GP  [SE361414H178]  32.49 60 90 bottom
PT5101  ST220U2VDM-5-GP  [CT7343H83]  102.45 115.93 90 bottom
PT5102  ST220U6D3VBM-3-GP  [CT3528H79]  121.01 114.28 270 bottom
PT5103  SE33U25VM-11-GP  [CT7343H83]  116.9 139.19 270 bottom
PU4301  AON7403-GP-U  [PPAK-8P-3232H36]  143.26 160.33 270 top
PU4402  AON7403-GP-U  [PPAK-8P-3232H36]  147.35 160.91 180 top
PU4403  AON7403-GP-U  [PPAK-8P-3232H36]  159.67 171.33 0 top
PU4404  BQ24727RGRR-1-GP  [QFN20G3D5-G2D15H40]  160.94 151.26 90 top
PU4405  AON7410-GP  [PPAK-8P-3232H36]  164.83 160.91 180 top
PU4406  AON7410-GP  [PPAK-8P-3232H36]  169.27 162.44 0 top
PU4501  AON7410-GP  [PPAK-8P-3232H36]  42.77 40.31 270 top
PU4502  AON7506-GP  [PPAK-8P-3232H36]  41.27 44.73 90 top
PU4503  TPS51225RUKR-GP  [QFN20-G1D75H32]  50.93 48.59 270 top
PU4504  AON7410-GP  [PPAK-8P-3232H36]  42.77 56.16 270 top
PU4505  AON7410-GP  [PPAK-8P-3232H36]  41.27 51.73 90 top
PU5001  RT5073BWGQW-GP  [QFN52J6-G4D75H32]  133.46 130.3 180 bottom
PU5101  AON7410-GP  [PPAK-8P-3232H36]  102.22 127.76 180 top
PU5102  AON7410-GP  [PPAK-8P-3232H36]  108.77 129.26 0 top
PU5103  AON7410-GP  [PPAK-8P-3232H36]  64.45 31.57 90 top
PU5104  AON7506-GP  [PPAK-8P-3232H36]  65.97 36.07 270 top
PU5105  FDMS3600-02-RJK0215-COLAY-GP  [PPAK-8P-G5324H44-COLAY]  116.54 128.35 90 bottom
PU5106  RT9610BZQW-GP  [DFN8-G125065H32]  104.68 135.41 90 bottom
PU5107  RT9610BZQW-GP  [DFN8-G125065H32]  122.89 134.52 90 top
PU5108  RT9610BZQW-GP  [DFN8-G125065H32]  57.11 32.41 180 top
PWR1  ACES-CON4-88-GP  [50524-00401-001]  177.4 177.3 270 bottom
PWSW2  SW-TACT-130-GP-U  [TJE-533-S-V-T-R-744]  167.42 119.15 270 bottom
Q1601  2N7002K-2-GP  [SOT23DGS2D4H44]  84.56 71.86 90 top
Q1701  2N7002KDW-1-GP  [SOT-363H44]  96.4 85.75 90 bottom
Q1801  2N7002K-2-GP  [SOT23DGS2D4H44]  107.42 102.57 20 bottom
Q1802  2N7002K-2-GP  [SOT23DGS2D4H44]  159.8 67.77 90 top
Q1901  PJT138KA-GP  [SOT-363H44]  90.51 71.07 90 bottom
Q1902  2N7002KDW-1-GP  [SOT-363H44]  142.91 22.58 90 bottom
Q1903  PJT138KA-GP  [SOT-363H44]  66.5 64.52 90 top
Q1904  PJT138KA-GP  [SOT-363H44]  104.35 141.2 270 bottom
Q1905  2N7002KDW-1-GP  [SOT-363H44]  104.38 144.32 90 bottom
Q2101  PJA138KA-GP  [SOT23DGS2D4H44]  134.88 109.15 20 bottom
Q2102  PJA138KA-GP  [SOT23DGS2D4H44]  161.14 79.25 270 top
Q2103  2N7002K-2-GP  [SOT23DGS2D4H44]  164.95 79.25 90 top
Q2104  2N7002K-2-GP  [SOT23DGS2D4H44]  84.72 75.62 270 bottom
Q2401  LMBT3906LT1G-1-GP  [SOT23CBE2D4H44]  166.86 49.02 0 bottom
Q2402  2N7002K-2-GP  [SOT23DGS2D4H44]  172.12 76.79 90 bottom
Q2403  2N7002KDW-1-GP  [SOT-363H44]  167.34 72.82 180 bottom
Q2404  DMP2130L-7-GP  [SOT23DGS2D4H48]  163.91 76.76 180 bottom
Q2501  BAS40C-2-GP  [SOT-23-9H44]  27.03 20.58 270 top
Q2502  2N7002K-2-GP  [SOT23DGS2D4H44]  27.03 25.66 0 top
Q2601  LMBT3904LT1G-GP  [SOT23CBE2D4H44]  154.19 47.75 180 bottom
Q2602  2N7002K-2-GP  [SOT23DGS2D4H44]  161.86 75.11 0 top
Q2603  2N7002KDW-1-GP  [SOT-363H44]  74.3 64.42 90 bottom
Q2604  LMBT3904LT1G-GP  [SOT23CBE2D4H44]  159.7 87.63 0 top
Q2701  DMN3404L-7-1-GP  [SOT23DGS2D4H44]  147.92 22.44 270 bottom
Q2902  LMBT3904LT1G-GP  [SOT23CBE2D4H44]  151.34 15.7 270 bottom
Q2903  LMBT3904LT1G-GP  [SOT23CBE2D4H44]  146.26 15.27 90 bottom
Q2904  LMBT3904LT1G-GP  [SOT23CBE2D4H44]  149.46 6.5 0 bottom
Q2905  LMBT3904LT1G-GP  [SOT23CBE2D4H44]  149.77 11.61 180 bottom
Q2906  LMBT3904LT1G-GP  [SOT23CBE2D4H44]  141.93 26.08 0 bottom
Q2907  MMBT3906-4-GP  [SOT23CBE2D4H44]  149.22 26.41 90 bottom
Q2908  LMBT3904LT1G-GP  [SOT23CBE2D4H44]  145.54 26.33 0 bottom
Q4001  2N7002KDW-1-GP  [SOT-363H44]  142.27 111.56 180 bottom
Q4002  2N7002KDW-1-GP  [SOT-363H44]  139.15 111.74 180 bottom
Q4003  2N7002KDW-1-GP  [SOT-363H44]  126.88 120.47 180 bottom
Q5501  LMBT3904LT1G-GP  [SOT23CBE2D4H44]  110.88 157.43 90 top
Q5503  PJA138KA-GP  [SOT23DGS2D4H44]  100.03 171.66 90 top
Q5504  LMBT3904LT1G-GP  [SOT23CBE2D4H44]  95.61 156.82 180 top
Q5701  PJT138KA-GP  [SOT-363H44]  19.49 57.28 90 top
Q5702  2N7002K-2-GP  [SOT23DGS2D4H44]  17 55.32 0 bottom
Q5703  2N7002K-2-GP  [SOT23DGS2D4H44]  18.93 60.71 0 bottom
Q6301  PJA138KA-GP  [SOT23DGS2D4H44]  62.06 59.16 270 top
Q6401  DMN5L06K-7-GP  [SOT23DGS2D4H48]  163.23 3.96 0 bottom
Q6403  RN2418-GP  [SOT23CBE2D6H62]  169.98 9.4 90 bottom
Q6404  RN2418-GP  [SOT23CBE2D6H62]  167.04 5.39 0 bottom
Q6501  DMN3404L-7-1-GP  [SOT23DGS2D4H44]  157.3 135.97 90 top
Q6502  RN2418-GP  [SOT23CBE2D6H62]  163.58 87.25 0 top
Q6504  DMP2130L-7-GP  [SOT23DGS2D4H48]  135.21 20.07 0 bottom
Q6505  2N7002K-2-GP  [SOT23DGS2D4H44]  134.78 25.83 0 bottom
Q6508  PJA138KA-GP  [SOT23DGS2D4H44]  138.36 25 0 bottom
Q6509  2N7002K-2-GP  [SOT23DGS2D4H44]  147.23 18.82 270 bottom
Q7001  2N7002KDW-GP  [SOT-363H44]  163.63 82.86 90 top
R601  0R0402-PAD-2-GP  [0R0402-PAD-1]  145.97 83.58 90 top
R602  0R0603-PAD-2-GP-U  [0R0603-PAD-1-U]  145.63 89.05 90 top
R603  0R0805-PAD-2-GP-U  [0R0805-PAD-1-U]  145.42 87.45 270 top
R604  0R0603-PAD-2-GP-U  [0R0603-PAD-1-U]  145.63 90.35 90 top
R605  0R0603-PAD-2-GP-U  [0R0603-PAD-1-U]  146.18 85.32 180 top
R606  0R0603-PAD-2-GP-U  [0R0603-PAD-1-U]  145.63 91.7 90 top
R607  0R0603-PAD-2-GP-U  [0R0603-PAD-1-U]  147.81 106.94 90 bottom
R608  0R0603-PAD-2-GP-U  [0R0603-PAD-1-U]  143.95 95.2 90 top
R609  0R0603-PAD-2-GP-U  [0R0603-PAD-1-U]  145.9 104.52 0 bottom
R610  0R0603-PAD-2-GP-U  [0R0603-PAD-1-U]  147.81 105.54 90 bottom
R611  0R0402-PAD-2-GP  [0R0402-PAD-1]  104.6 98.53 220 bottom
R701  0R0805-PAD-2-GP-U  [0R0805-PAD-1-U]  143.75 105.34 90 bottom
R702  0R0603-PAD-2-GP-U  [0R0603-PAD-1-U]  87.05 69.62 90 bottom
R801  402R2F-GP  [R402H16]  142.96 92.94 200 bottom
R802  402R2F-GP  [R402H16]  137.12 89.41 100 top
R803  1MR2J-1-GP  [R402H16]  112.4 94.08 290 top
R804  100KR2J-1-GP  [R402H16]  112.58 99.49 200 bottom
R805  100KR2J-1-GP  [R402H16]  113.37 99.77 200 bottom
R808  100KR2J-1-GP  [R402H16]  110.01 105.41 110 bottom
R1201  0R0402-PAD-2-GP  [0R0402-PAD-1]  150.35 46.15 270 top
R1207  3K65R2F-1-GP  [R402H16]  121.93 31.17 90 top
R1208  3K65R2F-1-GP  [R402H16]  92.21 29.97 90 top
R1211  3K65R2F-1-GP  [R402H16]  122.82 30.28 90 top
R1212  3K65R2F-1-GP  [R402H16]  93.5 30.41 180 top
R1213  0R0402-PAD-2-GP  [0R0402-PAD-1]  150.35 47.04 270 top
R1501  4K7R2F-GP  [R402H16]  100.81 107 0 bottom
R1502  10KR2F-2-GP  [R402H16]  101 108.94 90 bottom
R1503  4K7R2F-GP  [R402H16]  99.91 107.01 0 bottom
R1504  4K7R2F-GP  [R402H16]  99.73 108.76 0 bottom
R1505  4K7R2F-GP  [R402H16]  98.18 108.74 0 bottom
R1506  4K7R2F-GP  [R402H16]  97.26 106.99 0 bottom
R1507  4K7R2F-GP  [R402H16]  97.31 108.69 0 bottom
R1508  10KR2F-2-GP  [R402H16]  96.37 108.69 0 bottom
R1509  4K7R2F-GP  [R402H16]  96.37 106.99 0 bottom
R1510  4K7R2F-GP  [R402H16]  104.25 87.2 270 top
R1511  4K7R2F-GP  [R402H16]  109.53 87.51 20 top
R1512  10KR2F-2-GP  [R402H16]  102.11 95.7 220 bottom
R1513  4K7R2F-GP  [R402H16]  104.3 88.09 270 top
R1514  10KR2F-2-GP  [R402H16]  105.85 95.86 200 bottom
R1515  4K7R2F-GP  [R402H16]  111.03 90.15 20 top
R1516  4K7R2F-GP  [R402H16]  108.52 100.51 290 bottom
R1517  4K7R2F-GP  [R402H16]  104.3 89 269.9 top
R1518  4K7R2F-GP  [R402H16]  100.77 94.59 220 bottom
R1519  10KR2F-2-GP  [R402H16]  111.56 91.24 20 top
R1520  4K7R2F-GP  [R402H16]  106.66 96.14 200 bottom
R1521  4K7R2F-GP  [R402H16]  98.18 106.99 0 bottom
R1522  10KR2F-2-GP  [R402H16]  102.79 96.25 220 bottom
R1523  10KR2F-2-GP  [R402H16]  106.1 97.31 110 bottom
R1524  4K7R2F-GP  [R402H16]  108.59 99.65 290 bottom
R1525  10KR2J-3-GP  [R402H16]  101.43 95.15 220 bottom
R1526  4K7R2F-GP  [R402H16]  108.06 90.5 20 top
R1601  402R2F-GP  [R402H16]  144.99 108.87 270 top
R1605  10KR2J-3-GP  [R402H16]  84.39 74.45 90 top
R1606  10KR2J-3-GP  [R402H16]  86.39 68.86 0 top
R1607  0R0402-PAD-2-GP  [0R0402-PAD-1]  86.39 67.13 0 top
R1701  1KR2J-1-GP  [R402H16]  98.58 89.31 270 bottom
R1702  0R0402-PAD-2-GP  [0R0402-PAD-1]  137.12 94.49 200 top
R1703  100KR2J-1-GP  [R402H16]  137.93 94.79 200 top
R1801  0R2J-2-GP  [R402H16]  99.07 107.01 180 bottom
R1802  0R2J-2-GP  [R402H16]  65.64 43.66 0 top
R1803  0R2J-2-GP  [R402H16]  109.1 78.79 320 top
R1804  0R0402-PAD-2-GP  [0R0402-PAD-1]  107.04 65.61 0 top
R1805  0R2J-2-GP  [R402H16]  104.68 105.64 270 bottom
R1806  51R2J-2-GP  [R402H16]  140.6 109.43 0 top
R1807  100KR2J-1-GP  [R402H16]  105.54 80.65 20 bottom
R1808  10KR2J-3-GP  [R402H16]  103.3 80.31 110 bottom
R1809  0R0402-PAD-2-GP  [0R0402-PAD-1]  114.64 101.68 110 bottom
R1810  10MR2J-L-GP  [R402H16]  97.67 81.18 180 bottom
R1811  10KR2J-3-GP  [R402H16]  101.89 65.64 0 top
R1812  51R2J-2-GP  [R402H16]  64.47 69.01 270 top
R1813  10KR2J-3-GP  [R402H16]  103.92 73.33 180 bottom
R1814  100KR2J-1-GP  [R402H16]  107.3 104.98 290 bottom
R1815  1KR2J-1-GP  [R402H16]  114.66 100.71 110 bottom
R1816  10KR2J-3-GP  [R402H16]  114.15 84.69 290 top
R1817  100KR2J-1-GP  [R402H16]  99.22 90.15 270 bottom
R1818  0R2J-2-GP  [R402H16]  105.57 91.19 180 top
R1819  1KR2J-1-GP  [R402H16]  110.57 95.38 90 top
R1823  20KR2J-L2-GP  [R402H16]  101.02 65.64 180 top
R1824  10KR2J-3-GP  [R402H16]  106.18 65.61 0 top
R1826  100KR2J-1-GP  [R402H16]  94.7 89.69 180 bottom
R1827  51R2J-2-GP  [R402H16]  127.19 107.88 180 top
R1828  51R2J-2-GP  [R402H16]  125.4 107.86 180 top
R1829  0R0402-PAD-2-GP  [0R0402-PAD-1]  103.11 70.39 180 bottom
R1830  0R0402-PAD-2-GP  [0R0402-PAD-1]  96.88 89.31 90 bottom
R1832  1KR2J-1-GP  [R402H16]  103.94 70.39 0 bottom
R1833  100R2J-2-GP  [R402H14]  139.71 109.43 180 top
R1834  10KR2J-3-GP  [R402H16]  105.93 105.95 0 bottom
R1835  1KR2J-1-GP  [R402H16]  104.33 76.81 90 bottom
R1836  1KR2J-1-GP  [R402H16]  100.18 65.64 180 top
R1905  33R2J-2-GP  [R402H16]  107.36 81.29 110 top
R1907  200KR2F-L-GP  [R402H16]  132.09 104.95 290 bottom
R1908  33R2J-2-GP  [R402H16]  104.31 82.51 290 bottom
R1909  0R0402-PAD-2-GP  [0R0402-PAD-1]  101.38 93.27 90 bottom
R1911  0R2J-2-GP  [R402H16]  69.22 63.17 270 top
R1912  0R2J-2-GP  [R402H16]  67.04 66.65 270 top
R1919  0R0402-PAD-2-GP  [0R0402-PAD-1]  103 81.08 290 bottom
R1921  10KR2J-3-GP  [R402H16]  162.85 68.1 90 top
R1922  1KR2J-1-GP  [R402H16]  150.73 62.77 180 bottom
R1923  1KR2J-1-GP  [R402H16]  101.96 80.24 200 bottom
R1924  0R0402-PAD-2-GP  [0R0402-PAD-1]  98.2 88.44 270 bottom
R2001  60D4R2F-GP  [R402H16]  125.97 95.2 290 top
R2002  200R2F-L-GP  [R402H16]  111.26 80.22 120 top
R2003  137R2F-GP  [R402H16]  130.92 91.15 110 top
R2004  113R2F-GP  [R402H16]  131.22 92.97 110 top
R2005  150R2F-1-GP  [R402H16]  123.71 94.46 110 top
R2006  200R2F-L-GP  [R402H16]  120.4 94.03 110 top
R2007  150R2F-1-GP  [R402H16]  123.32 95.2 110 top
R2008  200R2F-L-GP  [R402H16]  110.62 85.09 20 top
R2009  150R2F-1-GP  [R402H16]  138.74 86.03 190 top
R2010  105R2F-GP  [R402H16]  132.63 74.26 290 bottom
R2011  105R2F-GP  [R402H16]  125.46 80.55 20 top
R2012  100KR2J-1-GP  [R402H16]  113.29 86.4 290 top
R2013  0R0402-PAD-2-GP  [0R0402-PAD-1]  169.65 49.56 0 top
R2014  0R2J-2-GP  [R402H16]  170.95 49.94 90 top
R2016  0R2J-2-GP  [R402H16]  104.01 83.33 290 bottom
R2017  0R2J-2-GP  [R402H16]  85.38 65.2 90 top
R2018  10KR2J-3-GP  [R402H16]  93.45 67.19 90 top
R2019  10KR2J-3-GP  [R402H16]  100.8 85.89 180 bottom
R2020  10KR2J-3-GP  [R402H16]  101.66 85.9 0 bottom
R2023  100KR2J-1-GP  [R402H16]  170.95 49.1 90 top
R2024  10KR2J-3-GP  [R402H16]  100.79 87.63 0 bottom
R2025  10KR2J-3-GP  [R402H16]  99.96 87.63 180 bottom
R2028  10KR2J-3-GP  [R402H16]  99.12 85.9 0 bottom
R2029  10KR2J-3-GP  [R402H16]  99.96 85.9 180 bottom
R2101  1KR2F-3-GP  [R402H16]  103.33 64.37 270 top
R2104  33R2J-2-GP  [R402H16]  105.34 65.61 180 top
R2105  33R2J-2-GP  [R402H16]  102.75 65.64 180 top
R2106  10KR2J-3-GP  [R402H16]  126.22 104.07 290 bottom
R2107  33R2J-2-GP  [R402H16]  90.53 63.15 90 top
R2114  10KR2J-3-GP  [R402H16]  115.12 99.98 110 bottom
R2115  100KR2J-1-GP  [R402H16]  135.39 111.81 110 bottom
R2116  4K7R2J-2-GP  [R402H16]  136.38 106.94 110 bottom
R2117  0R2J-2-GP  [R402H16]  116.26 101.3 290 bottom
R2118  0R2J-2-GP  [R402H16]  64.93 60.17 270 top
R2119  20KR2J-L2-GP  [R402H16]  64.96 59.29 90 top
R2120  10KR2J-3-GP  [R402H16]  158.83 80.19 180 top
R2121  249R2F-GP  [R402H16]  103.61 65.64 0 top
R2122  10KR2J-3-GP  [R402H16]  83.93 72.34 90 bottom
R2123  2K2R2J-2-GP  [R402H16]  85.1 78.28 180 bottom
R2124  10KR2J-3-GP  [R402H16]  167.32 80.16 180 top
R2125  20KR2J-L2-GP  [R402H16]  59.24 59.03 89.7 top
R2126  10KR2J-3-GP  [R402H16]  169.58 77.93 180 top
R2128  0R0402-PAD-2-GP  [0R0402-PAD-1]  105.67 104.4 110 bottom
R2129  0R0402-PAD-2-GP  [0R0402-PAD-1]  168.31 78.36 270 top
R2400  10KR2J-3-GP  [R402H16]  154.85 64.16 270 bottom
R2401  33R2J-2-GP  [R402H16]  163.76 49.02 180 bottom
R2404  0R2J-2-GP  [R402H16]  165.77 52.2 270 top
R2405  10KR2J-3-GP  [R402H16]  165.31 49.02 180 top
R2408  2D2R3-1-U-GP  [R603H22]  177.07 60.81 270 bottom
R2411  0R2J-2-GP  [R402H16]  172.68 71.22 180 bottom
R2412  0R2J-2-GP  [R402H16]  161.09 49.02 180 bottom
R2414  0R0402-PAD-2-GP  [0R0402-PAD-1]  173.57 71.22 180 bottom
R2415  0R0402-PAD-2-GP  [0R0402-PAD-1]  158.05 48.41 0 bottom
R2416  33R2J-2-GP  [R402H16]  161.98 49.02 180 bottom
R2418  33R2J-2-GP  [R402H16]  160.21 49.02 180 bottom
R2419  1KR2J-1-GP  [R402H16]  149.41 64.44 180 bottom
R2421  10KR2J-3-GP  [R402H16]  149.41 66.14 180 bottom
R2422  0R0402-PAD-2-GP  [0R0402-PAD-1]  162.69 70.87 180 bottom
R2425  0R0402-PAD-2-GP  [0R0402-PAD-1]  154.85 61.5 90 bottom
R2426  10KR2J-3-GP  [R402H16]  167.93 49.05 180 top
R2427  10KR2J-3-GP  [R402H16]  152.15 57.74 270 top
R2430  10KR2F-2-GP  [R402H16]  165.23 71.43 180 bottom
R2435  0R0603-PAD-2-GP-U  [0R0603-PAD-1-U]  154.95 52.78 180 bottom
R2436  10KR2J-3-GP  [R402H16]  153.4 67.41 270 bottom
R2437  47KR2J-2-GP  [R402H16]  156.45 52.38 90 bottom
R2438  100KR2F-L1-GP  [R402H16]  156.01 53.65 0 bottom
R2439  100KR2J-1-GP  [R402H16]  157.61 49.68 270 bottom
R2440  100KR2J-1-GP  [R402H16]  166.43 65.1 270 top
R2441  10KR2J-3-GP  [R402H16]  156.65 46.43 0 bottom
R2442  100KR2J-1-GP  [R402H16]  171.41 71.73 270 bottom
R2443  100KR2F-L1-GP  [R402H16]  157.49 46.43 180 bottom
R2444  0R0402-PAD-2-GP  [0R0402-PAD-1]  170.92 73.1 0 bottom
R2445  8K2R2J-3-GP  [R402H16]  154.85 63.27 270 bottom
R2462  10KR2J-3-GP  [R402H16]  172.24 48.64 0 bottom
R2468  1KR2J-1-GP  [R402H16]  170.37 47.63 90 bottom
R2471  10KR2J-3-GP  [R402H16]  154.85 59.72 270 bottom
R2472  10KR2J-3-GP  [R402H16]  168.82 49.05 180 top
R2473  10KR2J-3-GP  [R402H16]  153.98 57.74 90 top
R2489  330KR2J-L1-GP  [R402H16]  160 46.43 180 bottom
R2491  330KR2J-L1-GP  [R402H16]  163.08 74.45 270 bottom
R2492  20KR2J-L2-GP  [R402H16]  164.8 73.61 270 bottom
R2493  1KR2J-1-GP  [R402H16]  169.1 49.02 180 bottom
R2494  0R2J-2-GP  [R402H16]  174.4 71.22 180 bottom
R2497  0R0402-PAD-2-GP  [0R0402-PAD-1]  162.87 49.02 0 bottom
R2498  0R0402-PAD-2-GP  [0R0402-PAD-1]  154.85 65.05 270 bottom
R2499  0R0402-PAD-2-GP  [0R0402-PAD-1]  159.19 46.43 0 bottom
R2500  0R0402-PAD-2-GP  [0R0402-PAD-1]  169.91 49.38 0 bottom
R2501  0R0402-PAD-2-GP  [0R0402-PAD-1]  169.3 73.1 0 bottom
R2502  33R2J-2-GP  [R402H16]  56.55 47.42 90 top
R2503  0R0402-PAD-2-GP  [0R0402-PAD-1]  154.85 62.46 90 bottom
R2505  0R0402-PAD-2-GP  [0R0402-PAD-1]  154.85 60.61 90 bottom
R2506  0R0402-PAD-2-GP  [0R0402-PAD-1]  170.11 73.1 0 bottom
R2507  0R0402-PAD-2-GP  [0R0402-PAD-1]  153.88 56.34 0 bottom
R2508  0R0402-PAD-2-GP  [0R0402-PAD-1]  154.87 66.4 0 bottom
R2509  0R0402-PAD-2-GP  [0R0402-PAD-1]  163.58 70.87 180 bottom
R2510  0R0402-PAD-2-GP  [0R0402-PAD-1]  66.76 49.71 270 top
R2511  0R2J-2-GP  [R402H16]  160.26 71.2 0 bottom
R2512  0R0402-PAD-2-GP  [0R0402-PAD-1]  160.38 74.47 90 bottom
R2513  0R0402-PAD-2-GP  [0R0402-PAD-1]  56.55 45.29 90 top
R2514  0R0402-PAD-2-GP  [0R0402-PAD-1]  63.76 48.64 270 top
R2515  0R2J-2-GP  [R402H16]  29.57 22.86 180 top
R2516  10MR2J-L-GP  [R402H16]  23.86 22.35 270 top
R2517  0R0402-PAD-2-GP  [0R0402-PAD-1]  56.55 49.18 90 top
R2518  0R2J-2-GP  [R402H16]  26.52 23.24 270 top
R2522  4K7R2J-2-GP  [R402H16]  163 33.1 180 bottom
R2523  4K7R2J-2-GP  [R402H16]  173.11 31.07 90 top
R2527  1KR2J-1-GP  [R402H16]  23.86 21.47 270 top
R2528  0R0402-PAD-2-GP  [0R0402-PAD-1]  161.58 30.63 270 bottom
R2529  0R0402-PAD-2-GP  [0R0402-PAD-1]  60.64 51.72 90 top
R2530  0R0402-PAD-2-GP  [0R0402-PAD-1]  173.57 29.77 180 top
R2531  0R0402-PAD-2-GP  [0R0402-PAD-1]  64.29 51.41 0 top
R2532  4K7R2J-2-GP  [R402H16]  63.41 51.41 0 top
R2533  3K3R2J-3-GP  [R402H16]  63.76 47.8 270 top
R2534  3K3R2J-3-GP  [R402H16]  84.94 69.67 270 bottom
R2535  4K7R2J-2-GP  [R402H16]  162.9 29.64 0 bottom
R2601  0R2J-2-GP  [R402H16]  162.92 72.82 90 top
R2602  0R2J-2-GP  [R402H16]  164.14 74.75 180 top
R2603  0R0402-PAD-2-GP  [0R0402-PAD-1]  165.44 75.19 270 top
R2605  18K7R2F-GP  [R402H16]  80.02 74.5 90 bottom
R2606  2KR2F-3-GP  [R402H16]  82.38 72.65 180 bottom
R2607  0R2J-2-GP  [R402H16]  161.96 71.99 90 top
R2608  24K9R2F-L-GP  [R402H16]  153.35 109.7 90 bottom
R2609  0R2J-2-GP  [R402H16]  160.26 72.65 90 top
R2610  NTC-100K-8-GP  [NTC-603H38]  153.27 106.94 270 bottom
R2611  0R0402-PAD-2-GP  [0R0402-PAD-1]  155.05 108.82 270 bottom
R2612  24K9R2F-L-GP  [R402H16]  153.07 110.57 270 bottom
R2613  2KR2J-1-GP  [R402H16]  165.44 74.37 270 top
R2705  0R0402-PAD-2-GP  [0R0402-PAD-1]  154.74 18.8 90 top
R2706  0R2J-2-GP  [R402H16]  153.18 26.07 90 bottom
R2707  0R2J-2-GP  [R402H16]  158.71 26.57 0 bottom
R2708  0R0805-PAD-2-GP-U  [0R0805-PAD-1-U]  152.66 27.41 270 bottom
R2709  22R2J-2-GP  [R402H16]  156.9 26.32 180 bottom
R2710  0R0402-PAD-2-GP  [0R0402-PAD-1]  166.66 24.41 180 top
R2711  100KR2J-1-GP  [R402H16]  164.45 23.5 0 top
R2712  0R5J-5-GP  [R805H24]  151.33 23.71 270 bottom
R2713  100KR2J-1-GP  [R402H16]  161.53 13.34 0 bottom
R2714  20KR2F-L-GP  [R402H16]  167.24 22.99 270 bottom
R2715  200KR2F-L-GP  [R402H16]  167.24 23.88 270 bottom
R2716  0R5J-5-GP  [R805H24]  151.33 21.88 270 bottom
R2717  2K2R2J-2-GP  [R402H16]  167.01 25.88 90 bottom
R2718  0R0402-PAD-2-GP  [0R0402-PAD-1]  177.07 70.87 0 bottom
R2719  0R0402-PAD-2-GP  [0R0402-PAD-1]  169.07 23.52 0 bottom
R2720  0R0603-PAD-2-GP-U  [0R0603-PAD-1-U]  168.61 11.23 0 top
R2721  22R2J-2-GP  [R402H16]  161.91 26.98 180 bottom
R2722  0R0402-PAD-2-GP  [0R0402-PAD-1]  155.38 25.02 270 bottom
R2723  22R2J-2-GP  [R402H16]  156.7 27.97 270 bottom
R2724  0R0402-PAD-2-GP  [0R0402-PAD-1]  155.25 19.05 180 bottom
R2725  0R0603-PAD-2-GP-U  [0R0603-PAD-1-U]  163.94 11.48 0 top
R2726  100KR2J-1-GP  [R402H16]  145.63 21.47 0 bottom
R2727  0R0603-PAD-2-GP-U  [0R0603-PAD-1-U]  159.77 12.12 0 top
R2728  0R0603-PAD-2-GP-U  [0R0603-PAD-1-U]  159.11 19.18 90 top
R2729  0R0402-PAD-2-GP  [0R0402-PAD-1]  165.35 26.35 180 bottom
R2730  1KR2J-1-GP  [R402H16]  176.21 70.87 0 bottom
R2733  100KR2J-1-GP  [R402H16]  157.23 27.87 0 top
R2901  0R0603-PAD-2-GP-U  [0R0603-PAD-1-U]  150.58 10.49 180 top
R2902  0R0603-PAD-2-GP-U  [0R0603-PAD-1-U]  153.38 10.72 270 top
R2903  0R0603-PAD-2-GP-U  [0R0603-PAD-1-U]  153.86 12.77 225 top
R2904  0R0603-PAD-2-GP-U  [0R0603-PAD-1-U]  154.77 13.68 225 top
R2906  0R0603-PAD-2-GP-U  [0R0603-PAD-1-U]  171.51 16.66 90 top
R2907  0R0603-PAD-2-GP-U  [0R0603-PAD-1-U]  169.43 14.05 0 top
R2908  10R2F-L-GP  [R402H14]  160.76 17.4 180 top
R2909  0R0603-PAD-2-GP-U  [0R0603-PAD-1-U]  170.19 18.34 0 bottom
R2910  10R2F-L-GP  [R402H14]  163.18 14.78 90 top
R2911  0R0603-PAD-2-GP-U  [0R0603-PAD-1-U]  171.58 18.04 90 top
R2912  4K7R2J-2-GP  [R402H16]  161.65 17.4 180 top
R2913  4K7R2J-2-GP  [R402H16]  163.18 15.62 90 top
R2914  0R0603-PAD-2-GP-U  [0R0603-PAD-1-U]  169.2 14.07 90 bottom
R2915  8K2R2J-L-2-GP  [R402H16]  150.41 14.11 180 top
R2916  8K2R2J-L-2-GP  [R402H16]  151.24 18.8 270 top
R2917  10KR2J-3-GP  [R402H16]  167.55 14.28 0 top
R2918  10KR2J-3-GP  [R402H16]  168.26 17.86 0 bottom
R2919  1KR2J-1-GP  [R402H16]  168.74 16.18 270 bottom
R2920  1KR2J-1-GP  [R402H16]  167.11 13.85 270 bottom
R2921  22KR2J-GP  [R402H16]  147.48 7.95 270 top
R2922  8K2R2J-L-2-GP  [R402H16]  152.69 9.04 0 top
R2923  8K2R2J-L-2-GP  [R402H16]  149.53 10.47 0 top
R2924  10KR2F-2-GP  [R402H16]  151.17 24.83 180 top
R2925  10KR2F-2-GP  [R402H16]  150.34 24.85 0 top
R2926  10KR2F-2-GP  [R402H16]  149.52 23.79 180 top
R2927  1KR2J-1-GP  [R402H16]  152.37 29.19 270 bottom
R2928  10KR2F-2-GP  [R402H16]  155.2 28.42 0 top
R2929  1KR2J-1-GP  [R402H16]  156.39 27.87 0 top
R2930  22KR2J-GP  [R402H16]  150.4 15.8 180 top
R3502  0R0402-PAD-2-GP  [0R0402-PAD-1]  25.79 32.69 90 bottom
R3503  0R0402-PAD-2-GP  [0R0402-PAD-1]  25.79 33.53 90 bottom
R3601  100KR2J-1-GP  [R402H16]  18.78 35.31 0 top
R4002  100KR2J-1-GP  [R402H16]  142.6 114.48 180 bottom
R4003  1KR2J-1-GP  [R402H16]  142.07 109.2 90 bottom
R4004  0R0402-PAD-2-GP  [0R0402-PAD-1]  24.47 52.61 90 top
R4005  0R2J-2-GP  [R402H16]  128.38 118.21 270 bottom
R4006  1KR2J-1-GP  [R402H16]  138.41 109.48 270 bottom
R4007  1KR2J-1-GP  [R402H16]  50.81 52.99 270 bottom
R4008  0R2J-2-GP  [R402H16]  22.49 57.94 90 bottom
R4009  100KR2J-1-GP  [R402H16]  140.19 114.58 0 bottom
R4010  0R2J-2-GP  [R402H16]  25.71 57.69 90 bottom
R4011  100KR2J-1-GP  [R402H16]  128.84 121.29 0 bottom
R4012  470R2J-2-GP  [R402H16]  126.68 118.21 90 bottom
R4013  1KR2J-1-GP  [R402H16]  53.78 54.26 180 top
R4049  0R3J-0-U-GP  [R603H22]  127.13 116.51 0 bottom
R4050  0R0603-PAD-2-GP-U  [0R0603-PAD-1-U]  125.84 116.51 0 bottom
R4301  0R0402-PAD-2-GP  [0R0402-PAD-1]  154.06 178.67 90 top
R5501  100KR2J-1-GP  [R402H16]  108.8 177.5 270 top
R5502  100KR2J-1-GP  [R402H16]  104.5 171.12 270 top
R5503  100KR2J-1-GP  [R402H16]  103.11 156.19 90 top
R5504  0R0402-PAD-2-GP  [0R0402-PAD-1]  104.86 156.19 270 top
R5505  0R0402-PAD-2-GP  [0R0402-PAD-1]  116.19 177.17 90 top
R5506  0R0402-PAD-2-GP  [0R0402-PAD-1]  119.64 164.44 0 top
R5507  0R5J-5-GP  [R805H24]  103.64 163.37 0 top
R5510  0R2J-2-GP  [R402H16]  114.71 160.2 270 top
R5512  0R0603-PAD-2-GP-U  [0R0603-PAD-1-U]  125.51 165.64 0 top
R5514  100KR2J-1-GP  [R402H16]  99.52 173.99 270 top
R5515  100KR2J-1-GP  [R402H16]  108.26 166.52 270 top
R5516  0R0402-PAD-2-GP  [0R0402-PAD-1]  118.8 164.44 0 top
R5517  0R0402-PAD-2-GP  [0R0402-PAD-1]  110.5 177.5 270 top
R5518  0R0402-PAD-2-GP  [0R0402-PAD-1]  102.8 170.64 270 top
R5519  100R2J-2-GP  [R402H14]  107.47 177.95 0 top
R5520  100KR2J-1-GP  [R402H16]  106.48 166.52 270 top
R5522  0R3J-0-U-GP  [R603H22]  122.56 165.58 180 top
R5523  0R3J-0-U-GP  [R603H22]  125.53 170.51 0 top
R5525  0R3J-0-U-GP  [R603H22]  115.3 179.05 270 top
R5526  100KR2J-1-GP  [R402H16]  114.71 161.04 90 top
R5527  100KR2J-1-GP  [R402H16]  113.34 160.1 0 top
R5528  100KR2J-1-GP  [R402H16]  94.22 154.33 90 top
R5529  2K2R2J-2-GP  [R402H16]  98.23 156.77 0 top
R5530  2K2R2J-2-GP  [R402H16]  96.15 159.23 90 top
R5531  2K2R2J-2-GP  [R402H16]  110.37 159.67 270 top
R5532  2K2R2J-2-GP  [R402H16]  112.07 159.67 90 top
R5533  100R2J-2-GP  [R402H14]  117.94 177.29 270 top
R5534  20R2J-3-GP  [R402H16]  113.42 168.43 180 bottom
R5535  0R2J-2-GP  [R402H16]  114.28 168.43 180 bottom
R5536  10KR2J-3-GP  [R402H16]  112.3 167.9 0 bottom
R5537  0R2J-2-GP  [R402H16]  111.13 167.87 0 bottom
R5538  100R2J-2-GP  [R402H14]  110.29 167.87 180 bottom
R5701  0R0402-PAD-2-GP  [0R0402-PAD-1]  15.02 59.13 270 top
R5702  100KR2J-1-GP  [R402H16]  15.02 58.27 90 top
R5703  10KR2J-3-GP  [R402H16]  20.68 63.68 90 bottom
R5704  150R2F-1-GP  [R402H16]  18.04 49.27 180 top
R5705  150R2F-1-GP  [R402H16]  18.04 47.59 180 top
R5706  150R2F-1-GP  [R402H16]  18.04 45.87 180 top
R5707  150R2F-1-GP  [R402H16]  18.04 50.97 180 top
R5718  0R0603-PAD-2-GP-U  [0R0603-PAD-1-U]  16.49 59.01 0 bottom
R6001  0R0402-PAD-2-GP  [0R0402-PAD-1]  169.65 43.69 270 bottom
R6002  0R0402-PAD-2-GP  [0R0402-PAD-1]  169.81 142.06 270 top
R6003  0R2J-2-GP  [R402H16]  169.81 142.06 90 bottom
R6004  0R0805-PAD-2-GP-U  [0R0805-PAD-1-U]  170.85 146.64 270 bottom
R6005  10KR2J-3-GP  [R402H16]  166.17 37.09 90 bottom
R6006  0R0402-PAD-2-GP  [0R0402-PAD-1]  167.19 39.65 90 top
R6007  10KR2J-3-GP  [R402H16]  165.95 46.08 0 bottom
R6008  10KR2J-3-GP  [R402H16]  164.22 46.08 180 bottom
R6009  0R0402-PAD-2-GP  [0R0402-PAD-1]  167.11 42.8 90 top
R6010  0R0402-PAD-2-GP  [0R0402-PAD-1]  151.92 41.84 90 top
R6011  0R0402-PAD-2-GP  [0R0402-PAD-1]  151.92 40.95 90 top
R6012  4K7R2J-2-GP  [R402H16]  169.96 38.43 180 bottom
R6013  10KR2J-3-GP  [R402H16]  163.18 37.09 180 bottom
R6014  10KR2J-3-GP  [R402H16]  163.2 45.75 0 bottom
R6015  0R0402-PAD-2-GP  [0R0402-PAD-1]  151.92 42.72 90 top
R6016  4K7R2J-2-GP  [R402H16]  169.12 38.43 0 bottom
R6017  10KR2J-3-GP  [R402H16]  167.42 36.65 0 bottom
R6018  0R0402-PAD-2-GP  [0R0402-PAD-1]  167.11 41.91 90 top
R6019  0R0402-PAD-2-GP  [0R0402-PAD-1]  167.19 40.46 90 top
R6020  4K7R2J-2-GP  [R402H16]  162.36 45.75 0 bottom
R6021  10KR2J-3-GP  [R402H16]  164.45 37.09 90 bottom
R6022  4K7R2J-2-GP  [R402H16]  161.48 45.75 180 bottom
R6023  0R0402-PAD-2-GP  [0R0402-PAD-1]  151.92 43.61 90 top
R6024  10KR2J-3-GP  [R402H16]  165.11 46.08 180 bottom
R6025  0R0805-PAD-2-GP-U  [0R0805-PAD-1-U]  177.07 50.55 90 bottom
R6105  0R0603-PAD-2-GP-U  [0R0603-PAD-1-U]  146.74 147.93 270 top
R6106  0R2J-2-GP  [R402H16]  145.04 147.32 180 top
R6107  0R2J-2-GP  [R402H16]  142.58 152.07 180 top
R6108  0R2J-2-GP  [R402H16]  141.74 152.07 180 top
R6310  0R2J-2-GP  [R402H16]  52.84 61.93 90 top
R6311  0R2J-2-GP  [R402H16]  53.75 59.04 180 top
R6312  0R2J-2-GP  [R402H16]  59.24 59.9 90 top
R6314  0R2J-2-GP  [R402H16]  66.58 57.53 270 bottom
R6315  0R2J-2-GP  [R402H16]  66.61 61.75 270 bottom
R6317  0R2J-2-GP  [R402H16]  66.61 62.59 270 bottom
R6318  0R2J-2-GP  [R402H16]  66.57 56.67 270 bottom
R6319  0R2J-2-GP  [R402H16]  66.57 55.83 270 bottom
R6320  0R2J-2-GP  [R402H16]  66.61 60.89 270 bottom
R6321  0R2J-2-GP  [R402H16]  66.58 58.4 270 bottom
R6322  0R3J-0-U-GP  [R603H22]  48.72 61.55 180 top
R6323  0R2J-2-GP  [R402H16]  55.66 59.02 180 top
R6325  0R2J-2-GP  [R402H16]  66.61 60.02 270 bottom
R6327  0R3J-0-U-GP  [R603H22]  62.24 62.33 180 top
R6404  0R0402-PAD-2-GP  [0R0402-PAD-1]  165.87 2.14 90 bottom
R6405  0R0402-PAD-2-GP  [0R0402-PAD-1]  171.05 11.94 90 bottom
R6406  274R2F-GP  [R402H16]  169.63 5.26 180 bottom
R6407  422R2F-2-GP  [R402H16]  170.9 5.16 90 bottom
R6408  10KR2J-3-GP  [R402H16]  162.26 6.3 270 bottom
R6503  180KR2J-L-GP-U  [R402H16]  154.64 131.05 90 top
R6504  0R3J-0-U-GP  [R603H22]  154.42 128.91 90 top
R6505  100KR2J-1-GP  [R402H16]  160.43 137.01 270 top
R6506  1KR2J-1-GP  [R402H16]  162.52 90.5 180 top
R6507  100KR2J-1-GP  [R402H16]  154.69 130.06 90 top
R6508  0R0402-PAD-2-GP  [0R0402-PAD-1]  162.8 84.84 270 top
R6509  100KR2J-1-GP  [R402H16]  138.3 19.05 180 bottom
R6511  0R2J-2-GP  [R402H16]  145.7 30.61 90 top
R6513  4K7R2J-2-GP  [R402H16]  131.96 17.76 90 bottom
R6514  10KR2J-3-GP  [R402H16]  137.42 19.05 0 bottom
R6515  0R2J-2-GP  [R402H16]  143.97 30.61 270 top
R6516  1KR2J-1-GP  [R402H16]  168.16 63.73 270 top
R6517  0R3J-0-U-GP  [R603H22]  132.34 24.46 180 bottom
